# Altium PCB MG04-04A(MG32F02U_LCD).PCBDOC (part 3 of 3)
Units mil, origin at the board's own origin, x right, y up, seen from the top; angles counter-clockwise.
Board outline 5905.51 x 3543.31 mil, 2 copper layers (Top Layer, Bottom Layer); 293 components, 227 nets, 959 pads, 508 vias.
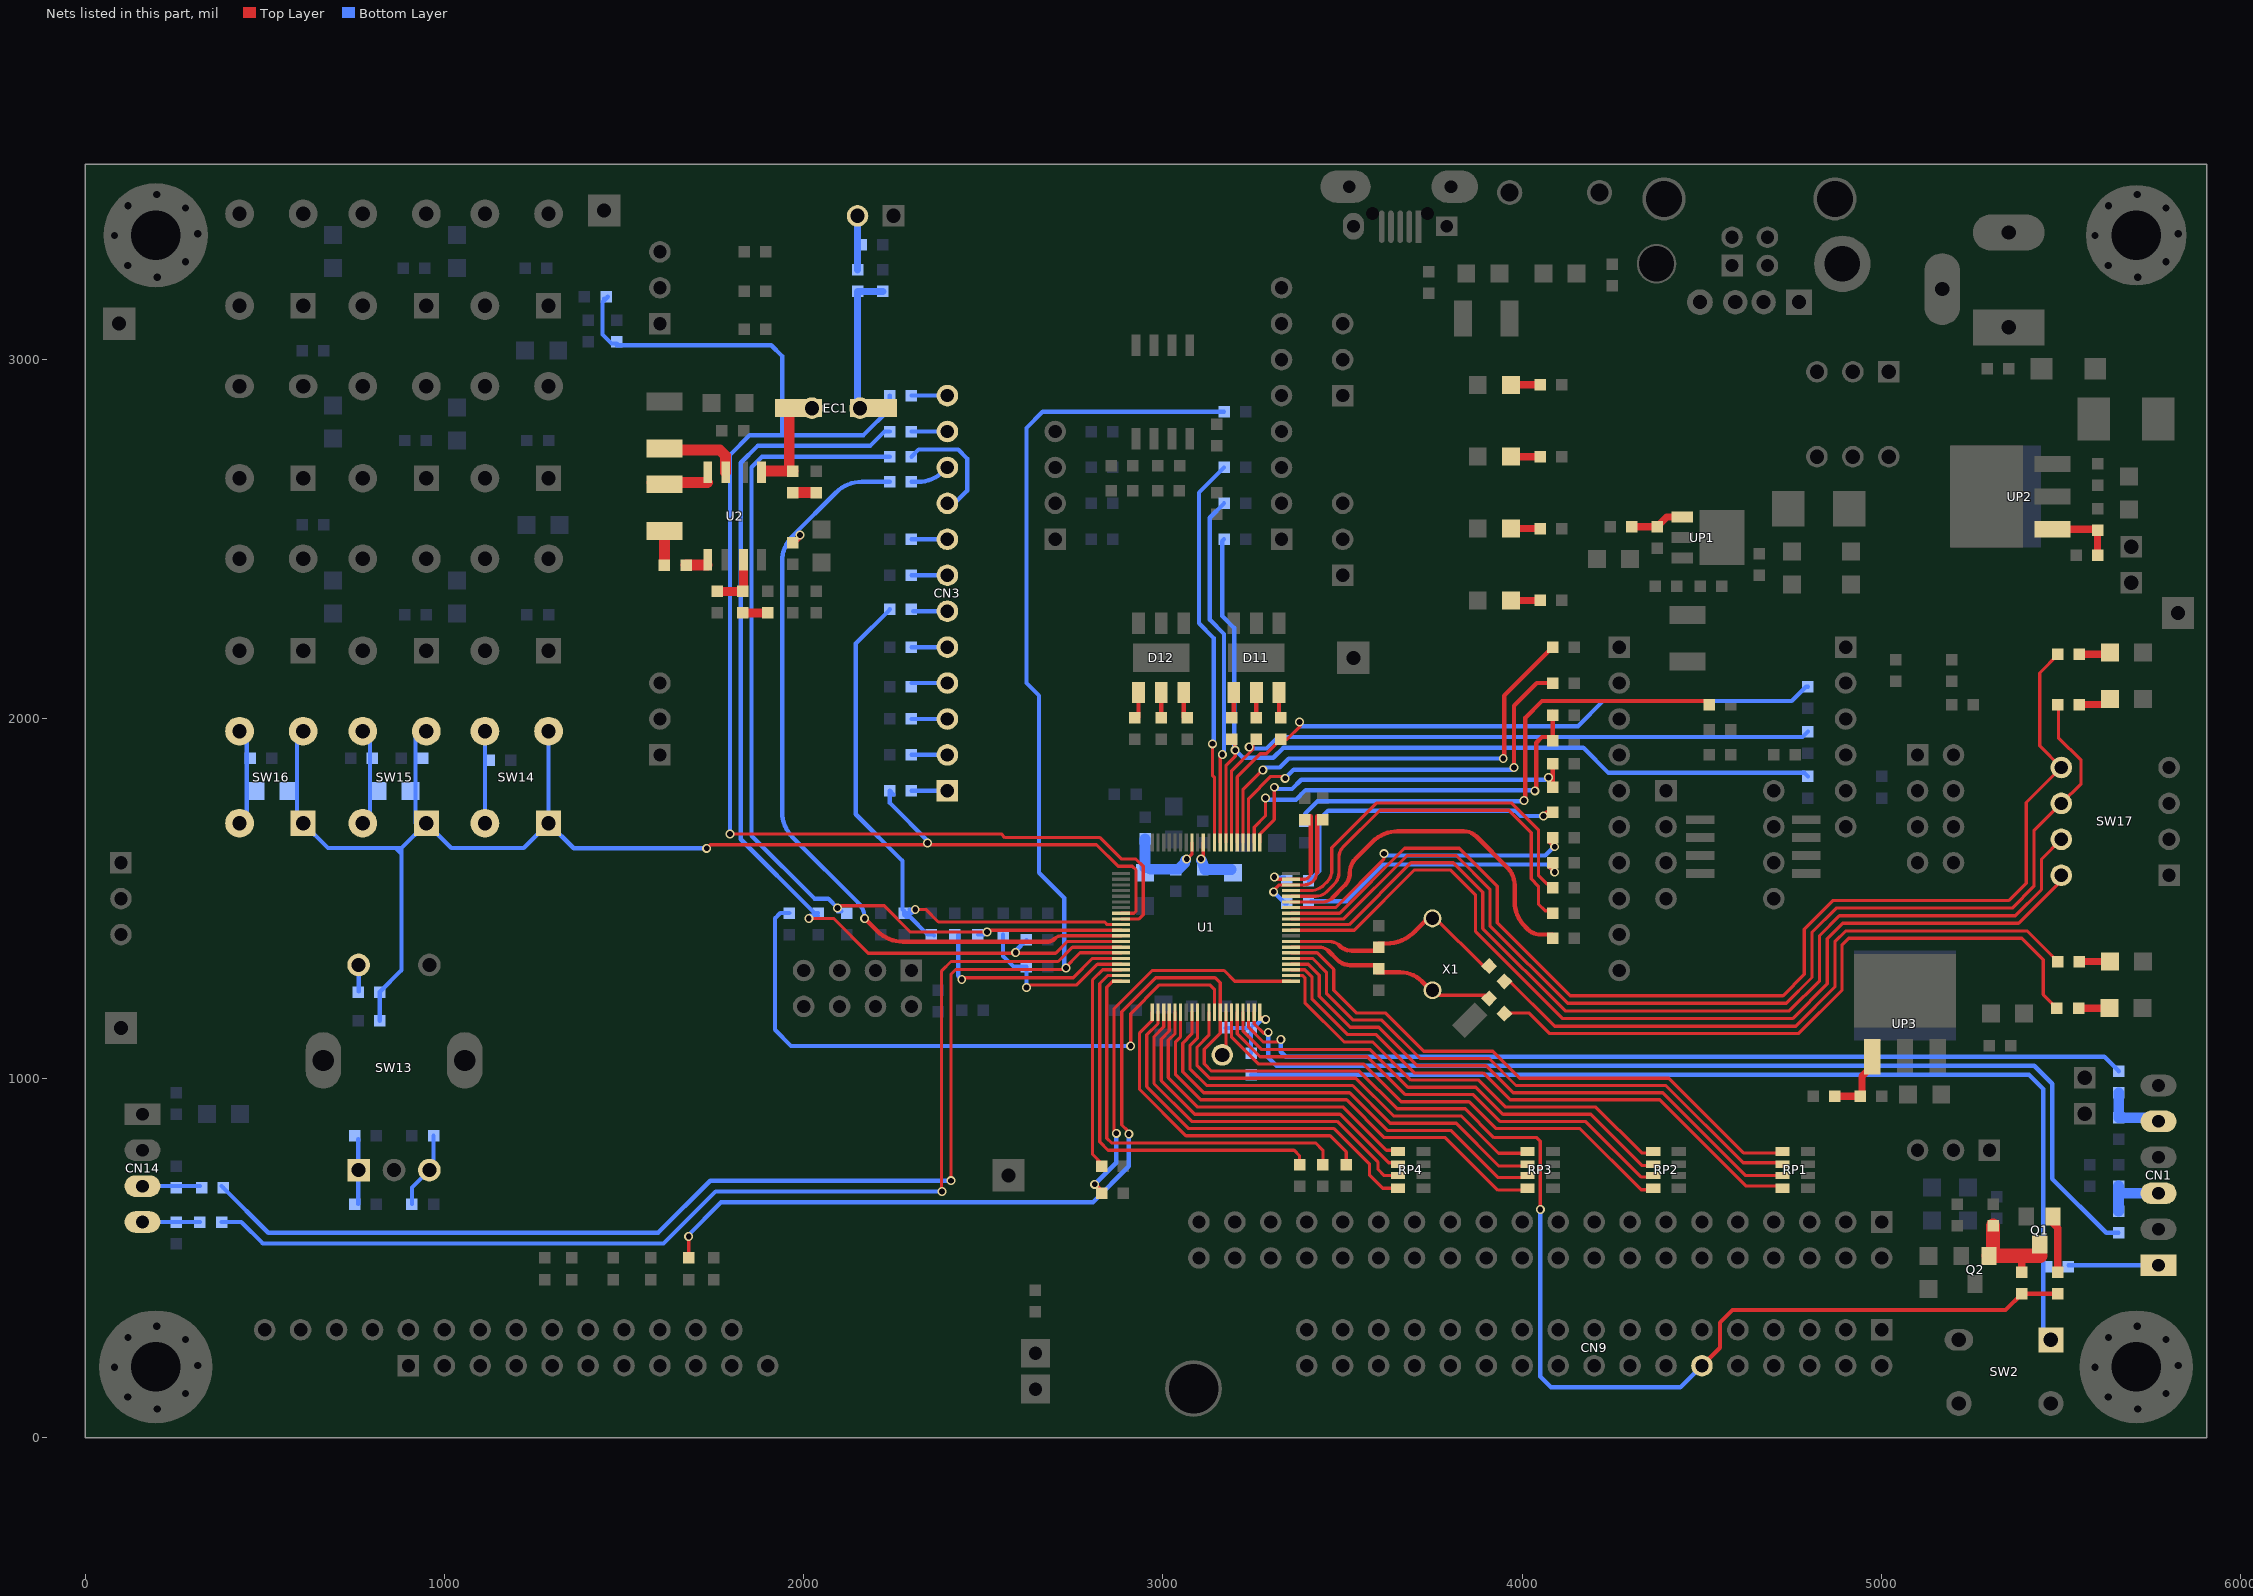
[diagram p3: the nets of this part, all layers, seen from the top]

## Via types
v1: diameter 25, hole 12, Top Layer to Bottom Layer, tented both sides, 253 vias
v2: diameter 25, hole 16, Top Layer to Bottom Layer, tented both sides, 83 vias
v3: diameter 20, hole 12, Top Layer to Bottom Layer, tented both sides, 77 vias
v4: diameter 35, hole 12, Top Layer to Bottom Layer, tented both sides, 64 vias
v5: diameter 40, hole 20, Top Layer to Bottom Layer, tented both sides, 16 vias
v6: diameter 30, hole 12, Top Layer to Bottom Layer, tented both sides, 13 vias
v7: diameter 28, hole 16, Top Layer to Bottom Layer, tented both sides, 2 vias

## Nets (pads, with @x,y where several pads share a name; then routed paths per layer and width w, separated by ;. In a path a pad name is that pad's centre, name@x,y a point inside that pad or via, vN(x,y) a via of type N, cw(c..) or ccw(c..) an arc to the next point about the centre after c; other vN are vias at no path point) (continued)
MG_PA14: C51.1 C52.1 C53.1 R37.2 R115.2 R123.2 SW14.1 SW14.3 SW15.1 SW15.3 SW16.1 SW16.3 U1.8 | length 4220.5
  Top Layer w9: v2(1730,1640) 1740,1650 2815,1650 2875,1590 2915,1590 2925,1580 2925,1465 2919.37,1459.37 U1.8@2883.78,1459.37
  Bottom Layer w12: SW16.1@590,1710 SW16.1@590,1727 ; SW16.3@590,1966 SW16.3@590,1949 ; SW16.3@607,1966 SW16.3@590,1949 ; R115.2@820,1160 R123.2@820,1240 881,1301 881,1625 ; SW15.1@920,1710 SW15.1@920,1716 ; SW15.3@920,1960 SW15.1@920,1716 ; SW15.1@930,1706 SW15.1@920,1716 ; SW15.1@930,1710 SW15.1@930,1720 ; SW14.3@1290,1966 SW14.1@1290,1710 ; v2(1730,1640) 1360,1640 SW14.1@1290,1710 ; R37.2@2250,1790 R37.2@2240,1800 2240,1766 v2@2350.5,1655.5 ; SW16.1@590,1727 SW16.1@607,1710 676,1641 865,1641 ; SW16.1@590,1727 SW16.3@590,1949 ; 865,1641 881,1641 ; 865,1641 881,1625 ; 881,1625 881,1641 ; 881,1641 SW15.1@950,1710 1019,1641 1221,1641 SW14.1@1290,1710
  other v2: 2345,1655
MG_PA15: C42.1 R46.2 R106.1 U1.9 | length 3836.7
  Top Layer w9: v2(1795,1680) 2550,1680 2560,1670 2825,1670 2885,1610 2925,1610 2945,1590 2945,1455 2933.62,1443.62 U1.9@2883.78,1443.62
  Bottom Layer w12: R106.1@1445,3170 1449,3170 R106.1@1449.5,3169.5 ; R106.1@1455,3175 R106.1@1449.5,3169.5 ; C42.1@1480,3040 1910,3040 1940,3010 1940,2790 ; C42.1@1480,3045 1465,3045 1440,3070 1440,3160 R106.1@1449.5,3169.5 ; v2(1795,1680) 1795,2735 1850,2790 1940,2790 ; R46.2@2240,2900 2240,2863.39 2166.61,2790 1940,2790
MG_PB0: R33.2 R47.2 R126.2 U1.10 | length 1701.7
  Top Layer w9: v2(2310.59,1470) 2340,1470 2375,1435 2837.87,1435 2845,1427.87 U1.10@2883.78,1427.87
  Bottom Layer w12: R33.2@2240,2305 2145,2210 2145,1735 2275,1605 2275,1470 2280,1465 R126.2@2280,1460 2280,1455 2285,1450 R126.2@2295,1450 ; R126.2@2295,1470 v2(2310.59,1470) 2300.59,1460 2285,1460 R126.2@2295,1450 ; R47.2@2362.5,1397.5 2360,1400 R47.2@2355,1400 2345,1400 R126.2@2295,1450
MG_PB1: R34.2 R48.2 R128.2 U1.11 | length 2639.8
  Top Layer w9: v2@2100.41,1480 2224.41,1480 2297.41,1407 v2(2510,1407) 2515.13,1412.13 2730,1412.13 ; 2690,1412.13 2730,1412.13 ; U1.11@2883.78,1412.13 2730,1412.13
  Bottom Layer w12: v2@2094.41,1465 R128.2@2105,1465 ; v2(2094.41,1474) 2068.41,1500 2030,1500 1855,1675 1855,2700.76 1884.24,2730 R34.2@2240,2730 ; R48.2@2485,1400 2503,1400 v2(2510,1407)
MG_PB2: R27.1 R35.2 U1.12 | length 2267.1
  Top Layer w9: 2699.18,1389.18 cw(c2716.56,1371.79) 2708.45,1395 ; 2710,1395 2708.45,1395 ; U1.12@2883.78,1396.38 2716.56,1396.38 ccw(c2716.56,1371.79) 2708.45,1395
  Top Layer w12: R27.1@1970,2484 v2@1995,2509 ; v2(2170,1445) 2205.73,1409.27 ccw(c2276.44,1479.98) 2276.44,1379.98 2676.98,1379.98 ccw(c2676.98,1411.37) 2699.15,1389.15
  Bottom Layer w12: v2(2170,1445) ccw(c2109.64,1445) 2152.32,1487.68 1969.29,1670.71 cw(c2040,1741.42) 1940,1741.42 1940,2438.58 cw(c2040,2438.58) 1969.29,2509.29 2090.9,2630.9 cw(c2161.61,2560.19) 2161.61,2660.19 R35.2@2240,2660.19
  other v2: 1990,2512
MG_PB3: R36.2 R129.2 R132.2 U1.13 | length 2792.1
  Top Layer w9: v2(2014.41,1445) 2083,1445 2180,1348 2701,1348 2733.63,1380.63 U1.13@2883.78,1380.63
  Bottom Layer w12: v2@2017,1452 R129.2@2039.59,1452 ; R129.2@2040,1460 2030,1460 1825,1665 1825,2713.19 1871.81,2760 2185,2760 2225,2800 R36.2@2240,2800 ; v2(2590,1350) 2590,1355 R132.2@2620,1385
MG_PB4: R59.1 U1.18 | length 621.3
  Top Layer w9: R59.1@2830,755 2830,762 2803.79,788.21 2803.79,1273.79 2831.89,1301.89 U1.18@2883.78,1301.89
MG_PB5: R63.1 U1.19 | length 1140.2
  Top Layer w9: U1.19@2883.78,1286.14 2846.14,1286.14 2823.79,1263.79 2823.79,823.21 2847,800 3080,800 ; 3046.72,800 3080,800 ; R63.1@3380,760 3380,785 3365,800 3080,800
MG_PB6: R62.1 U1.20 | length 1122.4
  Top Layer w9: U1.20@2883.78,1270.39 2860.39,1270.39 2843.79,1253.79 2843.79,833.21 2857,820 3425,820 3445,800 R62.1@3445,760
MG_PB7: R61.1 U1.21 | length 911.7
  Top Layer w9: U1.21@2970.39,1183.78 2970.39,1161.75 2935,1126.36 2935,968.73 3063.73,840 3465,840 3510,795 R61.1@3510,760
MG_PB8: RP4.4 U1.22 | length 1061.9
  Top Layer w9: U1.22@2986.14,1183.78 2986.14,1152.14 2955,1121 2955,977.01 3072.01,860 3476.27,860 3575,761.27 3575,730 3611.18,693.82 RP4.4@3649.57,693.82 ; RP4.4@3654.57,688.82 RP4.4@3649.57,693.82 ; RP4.4@3654.57,693.82 RP4.4@3649.57,693.82
MG_PB9: RP4.3 U1.23 | length 1014.8
  Top Layer w9: U1.23@3001.89,1183.78 3001.89,1143.1 2975,1116.21 2975,985.29 3080.29,880 3484.55,880 3598.77,765.78 3598.77,746.23 3615.75,729.25 RP4.3@3649.57,729.25 ; RP4.3@3648.82,730 RP4.3@3649.57,729.25 ; RP4.3@3654.57,724.25 RP4.3@3649.57,729.25 ; RP4.3@3654.57,729.25 RP4.3@3649.57,729.25
MG_PB10: RP4.2 U1.24 | length 957.7
  Top Layer w9: U1.24@3017.64,1183.78 3017.64,1131.64 2995,1109 2995,993.58 3088.58,900 3492.84,900 3627.84,765 3645.31,765 RP4.2@3654.57,755.75
MG_PB11: RP4.1 U1.25 | length 916.4
  Top Layer w9: U1.25@3033.39,1183.78 3033.39,1124.01 3015,1105.63 3015,1001.86 3096.86,920 3501.87,920 3621.87,800 3645.75,800 RP4.1@3654.57,791.18
MG_PB12: RP3.4 U1.26 | length 1292.2
  Top Layer w9: U1.26@3049.13,1183.78 3049.13,1116.13 3035,1102 3035,1010.15 3105.15,940 3511.12,940 3616.12,835 3786,835 3932.18,688.82 RP3.4@4014.57,688.82
MG_PB13: RP3.3 U1.28 | length 1257.4
  Top Layer w9: U1.28@3080.63,1183.78 3080.63,1123.63 3055,1098 3055,1018.43 3113.43,960 3519.41,960 3624.41,855 3801,855 3931.75,724.25 RP3.3@4014.57,724.25
MG_PB14: RP3.2 U1.29 | length 1217.7
  Top Layer w9: U1.29@3096.38,1183.78 3096.38,1112.38 3075,1091 3075,1026.72 3121.72,980 3527.69,980 3632.69,875 3816,875 3935.25,755.75 RP3.2@4014.57,755.75
MG_PB15: RP3.1 U1.31 | length 1183
  Top Layer w9: U1.31@3127.87,1183.78 3127.87,1119.87 3095,1087 3095,1035 3130,1000 3536.72,1000 3641.72,895 3830,895 3933.82,791.18 RP3.1@4014.57,791.18
MG_PC0: _ICKO1.1 U1.34 | length 128.7
  Top Layer w9: _ICKO1.1@3175,1054 _ICKO1.1@3175,1068.88 ; _ICKO1.1@3175.12,1070 U1.34@3175.12,1183.78
MG_PC1: RP2.4 U1.35 | length 1424.5
  Top Layer w9: U1.35@3190.87,1183.78 3190.87,1114.13 3265,1040 3557.72,1040 3662.72,935 3852,935 3927,860 4160.61,860 4330.61,690 RP2.4@4370,690
MG_PC2: RP2.3 U1.36 | length 1388.6
  Top Layer w9: U1.36@3206.61,1183.78 3206.61,1123.39 3270,1060 3568.43,1060 3673.43,955 3862.71,955 3937.71,880 4175.61,880 4330.18,725.43 RP2.3@4370,725.43
MG_PC3: RP2.2 U1.37 | length 1354.4
  Top Layer w9: U1.37@3222.36,1183.78 3222.36,1132.64 3275,1080 3576.72,1080 3681.72,975 3870.99,975 3945.99,900 4190.61,900 4333.69,756.93 RP2.2@4370,756.93
MG_PC4: R20.1 U1.38 | length 2537.1
  Top Layer w9: U1.38@3238.11,1183.78 3238.11,1141.89 3279,1101 v2@3328,1101
  Bottom Layer w12: v2(3328,1108) 3328,1074 3342,1060 5620,1060 R20.1@5660,1020
MG_PC5: R21.1 U1.39 | length 2876.3
  Top Layer w9: U1.39@3253.86,1183.78 3253.86,1151.14 3280,1125 v2@3293,1125
  Bottom Layer w12: v2(3293,1128) 3293,1058 3316,1035 5425,1035 5475,985 5475,720 5625,570 R21.1@5659.37,570
MG_PC6: C22.1 R15.1 R16.1 U1.40 | length 208.1
  Top Layer w9: U1.40@3271,1164 v2(3286,1164) ; U1.40@3274,1169 v2@3280,1169
  Bottom Layer w12: R15.1@3175.12,1140 C22.1@3245,1140 R16.1@3245,1070 ; C22.1@3251,1149 3260,1149 3275,1164 v2(3286,1164) v2@3292,1164
MG_PC7: R60.1 U1.41 | length 1095.5
  Top Layer w9: R60.1@2835,670 R60.1@2835,680 ; v2(2870,847) 2865,847 2863.79,848.21 2863.79,1193.79 2970,1300 3170,1300 3199.61,1270.39 U1.41@3356.22,1270.39
  Top Layer w12: v2(2810,705) R60.1@2822.5,692.5
  Bottom Layer w12: v2(2810,705) 2870,765 v2(2870,847)
MG_PC8: RP2.1 U1.42 | length 1259.3
  Top Layer w9: U1.42@3356.22,1286.14 3388.86,1286.14 3395,1280 3395,1210 3504,1101 3584,1101 3690,995 3879.28,995 3954.28,920 4204.61,920 4332.25,792.36 RP2.1@4370,792.36
MG_PC9: RP1.4 U1.43 | length 1658.9
  Top Layer w9: U1.43@3356.22,1301.89 3394.37,1301.89 3415,1281.26 3415,1220.15 3513.15,1122 3592.03,1122 3699.03,1015 3891,1015 3966,940 4383,940 4623,700 RP1.4@4730,700
MG_PC10: RP1.3 U1.44 | length 1646.4
  Top Layer w9: U1.44@3356.22,1317.64 3404.36,1317.64 3435,1287 3435,1228.43 3521.43,1142 3600.32,1142 3707.32,1035 3899.28,1035 3974.28,960 4391.28,960 4622.03,729.25 RP1.3@4724.57,729.25
MG_PC11: RP1.2 U1.45 | length 1637.9
  Top Layer w9: U1.45@3356.22,1333.39 3416.61,1333.39 3455,1295 3455,1236.72 3529.72,1162 3608.6,1162 3715.6,1055 3907.57,1055 3982.57,980 4399.57,980 4614.57,765 RP1.2@4724.57,765
MG_PC12: RP1.1 U1.46 | length 1632.9
  Top Layer w9: U1.46@3356.22,1349.13 3428.87,1349.13 3475,1303 3475,1245 3538,1182 3618.6,1182 3725.6,1075 3917.57,1075 3992.57,1000 4407.85,1000 4615.49,792.36 RP1.1@4724.57,792.36
MG_PC13: R74.2 R125.2 | length 1882.5
  Top Layer w9: R125.2@3950.11,1182 4018,1182 4075,1125 4769.25,1125 4890,1245.75 4890,1371.51 4908.49,1390 5390,1390 5450,1330 5450,1233 R74.2@5488,1195
MG_PC14: R76.2 R124.2 | length 1803.2
  Top Layer w9: R124.2@3963,1272 4090,1145 4760.97,1145 4870,1254.03 4870,1379.79 4900.21,1410 5405,1410 R76.2@5490,1325 ; R76.2@5492,1320 R76.2@5492,1325
MG_PD0: R83.1 U1.54 | length 836.6
  Top Layer w9: U1.54@3356.22,1475.12 3480.12,1475.12 ; 3480,1475 3480.12,1475.12 ; v2(3615,1625) 3615,1610 3480.12,1475.12
  Top Layer w12: R83.1@4074.71,1659.71 v2(4090,1644.41)
  Bottom Layer w12: v2@3615,1620 4064,1620 4088.41,1644.41 v2(4090,1644.41)
MG_PD1: R94.1 U1.55 | length 1001.8
  Top Layer w9: U1.55@3356.22,1490.87 3445,1490.87 ccw(c3445,1526.48) 3470.18,1501.3
  Top Layer w12: 3470.18,1501.3 3505.44,1536.55 ccw(c3469.8,1572.2) 3520.2,1572.2 cw(c3575.74,1572.2) 3536.47,1611.47 3583.26,1658.26 cw(c3653.97,1587.55) 3653.97,1687.55 ; 3651.59,1687.55 3653.97,1687.55 ; 3978.73,1536.54 3978.73,1492.69 ccw(c4078.73,1492.69) 4008.02,1421.98 4015.01,1414.99 ccw(c4051.21,1451.21) 4051.21,1400 R94.1@4085,1400 ; 3978.73,1537.54 ccw(c3906.31,1536.54) 3961.13,1583.87 3871.59,1673.41 ccw(c3837.45,1639.27) 3837.45,1687.55 3653.97,1687.55
MG_PD2: R91.1 U1.56 | length 1124.3
  Top Layer w9: U1.56@3356.22,1506.61 3425,1506.61 ; 3500.48,1642.48 ccw(c3525.82,1617.16) 3490,1617.16 3490,1573.46 cw(c3441.54,1573.46) 3475.81,1539.19 3456.12,1519.5 ; 3500.65,1642.65 3604,1746 3962.53,1746 4025,1683.53 4025,1555 4045,1535 4045,1485 4064,1466 R91.1@4086,1466 ; 3425,1506.61 ccw(c3425,1550.62) 3456.12,1519.5 ; 3425,1506.61 ccw(c3425,1550.62) 3456.12,1519.5
MG_PD3: R90.1 U1.57 | length 1122.1
  Top Layer w9: U1.57@3356.22,1522.36 3410,1522.36 ; R90.1@4085,1530 4075,1540 4070,1540 4045,1565 4045,1691.81 3970.81,1766 3594,1766 3470,1642 3470,1578 ; 3410,1522.36 ccw(c3410,1576.35) 3448.17,1538.17 ; 3410,1522.36 ccw(c3410,1576.35) 3448.17,1538.17 ; 3448.17,1538.17 3457.27,1547.27 ; 3457.27,1547.27 ccw(c3426.54,1578) 3470,1578 ; 3457.27,1547.27 ccw(c3426.54,1578) 3470,1578
MG_PD4: R19.2 R89.1 | length 750.4
  Top Layer w12: R89.1@4074.71,1589.71 v2(4090,1574.41)
  Bottom Layer w12: R19.2@3412,1493 3510,1493 3612,1595 4069.41,1595 v2(4090,1574.41)
MG_PD4X: R13.1 R19.1 U1.58 | length 355.9
  Top Layer w9: v2(3308,1519) 3308,1523 3323.11,1538.11 U1.58@3356.22,1538.11 3391.86,1538.11 ccw(c3391.86,1574.93) 3417.89,1548.89 ccw(c3393.84,1572.95) 3427.86,1572.95
  Top Layer w12: 3429,1572.95 R13.1@3429,1729
  Bottom Layer w12: v2(3308,1519) 3339.64,1487.36 R19.1@3345,1487.36
MG_PD5: R18.2 R87.1 | length 840.8
  Top Layer w12: v2@4065,1736 R87.1@4077,1748
  Bottom Layer w12: R18.2@3406.5,1548.5 3435,1577 3435,1720 3460,1745 3980,1745 3995,1730 v2(4059,1730)
MG_PD5X: R12.1 R18.1 U1.59 | length 302.7
  Top Layer w9: v2(3310,1560) 3316.14,1553.86 U1.59@3356.22,1553.86 3392.79,1553.86 ccw(c3392.79,1570.93) 3404.86,1558.86 ccw(c3387.96,1575.76) 3411.86,1575.76 ; v2@3310,1565 v2@3312.5,1562.5
  Top Layer w12: 3411,1572.31 3411,1729
  Bottom Layer w12: v2@3313,1558 R18.1@3338,1558
MG_PD6: R17.2 R85.1 | length 1426.1
  Top Layer w12: v2@4008,1768 4008,2003 4055,2050 4520,2050 R85.1@4530,2040
  Bottom Layer w12: R17.2@3395,1715 3395,1736 3430,1771 v2@4005,1771
  other v2: 4005,1773
MG_PD7: R82.1 R86.1 U1.61 | length 1010.8
  Top Layer w9: U1.61@3269.61,1656.22 3269.61,1679.61 3310,1720 v2(3310,1810)
  Top Layer w12: R86.1@4083,1808 R86.1@4085,1810 R82.1@4085,1875 R82.1@4085,1880
  Bottom Layer w12: v2@3310,1807 3312,1805 3359,1805 3385,1831 4063,1831 v2@4065,1833
  other v2: 4073,1837
MG_PD8: R81.1 R88.1 U1.62 | length 1156.1
  Top Layer w9: U1.62@3253.86,1656.22 3253.86,1698.86 3285,1730 v2(3285,1780)
  Top Layer w12: v2(4035,1800) 4039,1804 4039,1934 4055,1950 4085,1950 R81.1@4085,2010 R81.1@4085,2020
  Bottom Layer w12: v2@3285,1775 3370,1775 3397,1802 v2@4035,1802
MG_PD9: R80.1 U1.63 | length 1218.5
  Top Layer w9: U1.63@3238.11,1656.22 3238.11,1778.11 3300,1840 v2@3340,1840
  Top Layer w12: v2(3977,1865) 3977,2037 4040,2100 4065,2100 ; 4049,2100 4065,2100 ; R80.1@4085,2100 4065,2100
  Bottom Layer w12: v2(3340,1835) 3364,1859 v2@3977,1859
MG_PD10: R78.1 U1.64 | length 1268
  Top Layer w9: U1.64@3222.36,1656.22 3222.36,1803.36 v2@3274.5,1855.5
  Top Layer w12: v2@3950,1891 3950,2065 R78.1@4085,2200
  Bottom Layer w12: v2(3278,1858) 3285,1865 3325,1865 3350,1890 v2(3947,1890)
MG_PD11: R92.2 R96.1 U1.65 | length 1922.4
  Top Layer w9: U1.65@3206.61,1656.22 3206.61,1838.61 3271,1903 3287.46,1903 R92.2@3328,1943.54 3345.19,1943.54 3381.81,1980.17 v2@3381.81,1990
  Bottom Layer w12: v2@3382.5,1994.31 3382.67,1992.01 3383.59,1980 4155,1980 4225,2050 4690,2050 ; 4715,2050 4690,2050 ; R96.1@4795,2090 4790,2090 4750,2050 4690,2050
  other v2: 3380,1991.81
MG_PD12: R93.2 R97.1 U1.66 | length 1912.3
  Top Layer w9: U1.66@3190.87,1656.22 3190.87,1855.87 3250,1915 3250,1933.54 R93.2@3260,1943.54
  Bottom Layer w12: v2@3240,1917.54 3242.46,1920 3244.46,1918 3288,1918 3320,1950 4710,1950 ; 4730,1950 4710,1950 ; R97.1@4795,1965 4780,1950 4710,1950
  other v2: 3240,1922
MG_PD13: R52.2 R95.2 R98.1 U1.67 | length 2671.6
  Top Layer w9: U1.67@3175.12,1656.22 3175.12,1870.12 3201,1896 v2(3201,1913) ; R95.2@3190,1943.54 R95.2@3190,1945 ; v2@3200,1913 R95.2@3200,1943.54
  Bottom Layer w12: R52.2@3170,2500 3165,2495 3165,2286.46 3198,2253.46 v2@3198,1913 ; v2@3203.5,1911.5 3223,1892 3307,1892 3335,1920 4170,1920 4240,1850 4575,1850 ; 4700,1850 4575,1850 ; R98.1@4795,1840 4785,1850 4575,1850
MG_PD14: R53.2 U1.68 | length 989
  Top Layer w9: U1.68@3159.37,1656.22 3159.37,1895.37 v2(3165,1901)
  Bottom Layer w12: v2@3161,1895 3170,1904 3170,2236.46 3130,2276.46 3130,2560 R53.2@3170,2600
MG_PD15: R54.2 U1.69 | length 1091.1
  Top Layer w9: v2@3138,1928.81 3138,1842 3143.62,1836.38 U1.69@3143.62,1656.22
  Bottom Layer w12: v2(3138,1931) 3141,1934 3141,2225.46 3100,2266.46 3100,2630 R54.2@3170,2700
MG_PE0: R104.2 U1.14 | length 3231.1
  Top Layer w9: v2@2383.79,685 2383.79,1298.79 2410,1325 2708,1325 2747.88,1364.88 U1.14@2883.78,1364.88
  Bottom Layer w12: R104.2@380,600 435,600 495,540 1610,540 1755,685 v2(2385,685)
MG_PE1: R51.2 R103.2 U1.15 | length 5336.3
  Top Layer w9: v2(2410,715) 2410,1290 2422.5,1302.5 v2@2725,1302.5 ; v2@2725,1305 2769.13,1349.13 U1.15@2883.78,1349.13
  Bottom Layer w12: R103.2@380,700 R103.2@385,695 510,570 1595,570 1740,715 v2(2410,715) ; v2@2730,1304 2725,1309 2725,1501.81 2655,1571.81 2655,2065 2620,2100 2620,2810 2665,2855 R51.2@3170,2855
  other v2: 2730,1307
MG_PE2: R49.2 U1.16 | length 593
  Top Layer w9: v2@2440,1280 2750,1280 2803.39,1333.39 U1.16@2883.78,1333.39
  Bottom Layer w12: R49.2@2430,1400 2430,1285 2435,1280 v2@2435,1275
  other v2: 2440,1275
MG_PE3: R50.2 R133.2 U1.17 | length 495.1
  Top Layer w9: v2@2620,1250 v2@2625,1255 ; v2(2620,1253) 2627,1260 2760,1260 2817.64,1317.64 U1.17@2883.78,1317.64
  Bottom Layer w12: R50.2@2555,1400 2555,1340 2585,1310 R133.2@2620,1310 v2(2620,1253) v2@2620,1250
MG_PE8: R127.2 U1.32 | length 1789.9
  Top Layer w9: v2(2910,1090) 2910,1180 2990,1260 3130,1260 3143.62,1246.38 U1.32@3143.62,1183.78
  Bottom Layer w12: R127.2@1960,1460 1935,1460 1920,1445 1920,1135 1965,1090 v2(2910,1090)
MG_PE9: CN9.12 R66.1 R70.1 R73.1 U1.33 | length 5640.8
  Top Layer w9: R66.1@1680,500 v2(1680,560) ; v2@2900,855 2885,870 2885,1185 2980,1280 3145,1280 3159.37,1265.63 U1.33@3159.37,1183.78 3159.37,1125.37 3115,1081 3115,1040 3135,1020 3546.72,1020 3651.72,915 3841,915 3921,835 4040,835 4050,825 v2(4050,635)
  Top Layer w12: CN9.12@4500,200 4550,250 4550,320 4585,355 5345,355 R73.1@5390,400 R70.1@5490,400
  Bottom Layer w12: v2@1675,560 1770,655 2805,655 2905,755 v2(2905,845) ; v2(4050,635) 4050,170 4080,140 4440,140 CN9.12@4500,200
MG_PE12: SW17.8 U1.50 | length 2692
  Top Layer w9: U1.50@3356.22,1412.13 3532.13,1412.13 3700,1580 3800,1580 3870,1510 3870,1408.28 4112.09,1166.19 4752.19,1166.19 4848.81,1262.81 4848.81,1388.57 4891.43,1431.19 5381.19,1431.19 5500,1550 SW17.8@5500,1565
MG_PE13: SW17.7 U1.51 | length 2766.6
  Top Layer w9: U1.51@3356.22,1427.87 3517.87,1427.87 3690,1600 3808.28,1600 3890,1518.28 3890,1416.57 4119,1187.57 4743.33,1187.57 4827.43,1271.67 4827.43,1397.43 4882.57,1452.57 5372.33,1452.57 5445,1525.24 5445,1610 SW17.7@5500,1665
MG_PE14: R77.2 SW17.6 U1.52 | length 3160.3
  Top Layer w9: U1.52@3356.22,1443.62 3503.62,1443.62 3680,1620 3816.57,1620 3910,1526.57 3910,1424.85 4126.07,1208.79 4734.55,1208.79 4806.21,1280.45 4806.21,1406.21 4873.79,1473.79 5363.55,1473.79 5423.79,1534.03 5423.79,1688.79 SW17.6@5500,1765 5555,1820 5555,1885 5492,1948 R77.2@5492,2035
MG_PE15: R79.2 SW17.5 U1.53 | length 3277.8
  Top Layer w9: U1.53@3356.22,1459.37 3491.58,1459.37 3672.21,1640 3824.85,1640 3930,1534.85 3930,1433.14 4133.14,1230 4725.76,1230 4785,1289.24 4785,1415 4865,1495 5354.76,1495 5402.57,1542.81 5402.57,1767.57 SW17.5@5500,1865 5440,1925 5440,2128 R79.2@5492,2180
MG_VR0X: C19.1 C20.1 U1.71 | length 144.3
  Top Layer w9: v2(3106,1610) 3112.13,1616.13 U1.71@3112.13,1656.22
  Bottom Layer w30: v2@3107,1606 C20.1@3115,1586 ; C20.1@3116,1581 C19.1@3190,1581
MG_VREFX: C13.1 C14.1 R11.1 U1.73 | length 242.7
  Top Layer w9: v2@3066.84,1609.16 3080.63,1622.94 U1.73@3080.63,1656.22
  Bottom Layer w30: C13.1@2950,1586 R11.1@2950,1666 ; C13.1@2965,1582 3043.55,1582 3059.97,1598.41 v2@3063,1606
  other v2: 3066,1610
MX_G0: CN3.1 R37.1 | length 100
  Bottom Layer w12: R37.1@2300,1800 CN3.1@2400,1800
MX_G1: CN3.2 R38.1 | length 100
  Bottom Layer w12: R38.1@2300,1900 CN3.2@2400,1900
MX_G2: CN3.3 R39.1 | length 105
  Bottom Layer w12: R39.1@2300,2000 CN3.3@2400,2000 CN3.3@2400,1995
MX_G3: CN3.4 R40.1 | length 100
  Bottom Layer w12: R40.1@2300,2100 CN3.4@2400,2100
MX_G4: CN3.5 R41.1 | length 70
  Bottom Layer w12: R41.1@2300,2200 CN3.5@2370,2200
MX_G6: CN3.7 R42.1 | length 108.5
  Bottom Layer w12: R42.1@2300,2400 CN3.7@2400,2400 2405,2400 CN3.7@2402.5,2397.5
MX_G7: CN3.8 R43.1 | length 100
  Bottom Layer w12: R43.1@2300,2500 CN3.8@2400,2500
MX_G11: CN3.12 R46.1 | length 100
  Bottom Layer w12: R46.1@2300,2900 CN3.12@2400,2900
MX_MISO: CN3.9 R34.1 | length 327.3
  Bottom Layer w12: R34.1@2300,2730 2320,2750 2430,2750 2455,2725 2455,2635 CN3.9@2410,2590
MX_NSS: CN3.6 R33.1 | length 95
  Bottom Layer w12: R33.1@2305,2300 CN3.6@2400,2300
MX_RXD: CN3.11 R36.1 | length 100
  Bottom Layer w12: R36.1@2300,2800 CN3.11@2400,2800
MX_TXD: CN3.10 R35.1 | length 112.3
  Bottom Layer w12: R35.1@2300,2660 2318.58,2660 ccw(c2318.58,2760) 2389.29,2689.29 CN3.10@2400,2700
NetC28_1: C28.1 R25.1 | length 70
  Top Layer w25: R25.1@1830,2295 C28.1@1900,2295
NetC29_1: C29.1 EC1.1 U2.5 | length 262.1
  Top Layer w30: U2.5@1892.71,2690 C29.1@1970,2690 ; C29.1@1960,2695 1960,2855 1970,2865 EC1.1@1980.67,2865
NetC29_2: C29.2 R31.1 | length 65
  Top Layer w30: C29.2@1970,2630 R31.1@2035,2630
NetC30_1: C30.1 CN2.2 R26.2 | length 150
  Bottom Layer w20: R26.2@2150,3250 CN2.2@2150,3400
NetC52_2: C52.2 R121.2 SW15.2 SW15.4 | length 250
  Bottom Layer w12: SW15.2@793,1710 SW15.4@793,1960
NetC53_2: C53.2 R122.2 SW16.2 SW16.4 | length 272.6
  Bottom Layer w12: SW16.2@430,1710 450,1730 450,1946 SW16.4@430,1966
NetD1_1: D1.1 R1.2 | length 72
  Top Layer w20: D1.1@3980,2530 R1.2@4050,2530 ; R1.2@4050,2530 4051,2530.01 R1.2@4050,2530
NetD2_1: D2.1 R2.2 | length 77
  Top Layer w20: D2.1@3974,2730 R2.2@4050,2730 R2.2@4051,2730
NetD3_1: D3.1 R3.2 | length 77
  Top Layer w20: D3.1@3968,2330.01 R3.2@4045,2330.01
NetD4_1: D4.1 R4.2 | length 76
  Top Layer w20: D4.1@3974,2930 R4.2@4050,2930
NetD11_2: D11.2 R92.1 | length 70
  Top Layer w12: R92.1@3322.99,2003.54 D11.2@3322.99,2073.54
NetD11_4: D11.4 R93.1 | length 70
  Top Layer w12: R93.1@3260,2003.54 D11.4@3260,2073.54
NetD11_6: D11.6 R95.1 | length 70
  Top Layer w12: R95.1@3197.01,2003.54 D11.6@3197.01,2073.54
NetD12_2: D12.2 R100.1 | length 70
  Top Layer w12: R100.1@3057.99,2003.54 D12.2@3057.99,2073.54
NetD12_4: D12.4 R101.1 | length 70
  Top Layer w12: R101.1@2995,2003.54 D12.4@2995,2073.54
NetD12_6: D12.6 R102.1 | length 70
  Top Layer w12: R102.1@2932.01,2003.54 D12.6@2932.01,2073.54
NetEC1_2: EC1.2 R26.1 R32.1 | length 395
  Bottom Layer w20: EC1.2@2150,2865 R26.1@2150,3190 R32.1@2220,3190
NetQ1_1: Q1.1 R70.2 | length 141.2
  Top Layer w20: Q1.1@5477.4,596 5490,583.4 R70.2@5490,460
NetQ1_3: Q1.3 Q2.1 R67.1 R73.2 | length 253
  Top Layer w20: R73.2@5390,460 5390,506
  Top Layer w40: Q2.1@5297.4,506 Q2.1@5298.4,506 ; Q2.1@5310,510 R67.1@5310,590 ; Q2.1@5316,506 5390,506 5442,506
NetR5_2: R5.2 R7.1 UP2.1 | length 195.4
  Top Layer w20: UP2.1@5476,2528 5588,2528 R5.2@5601,2515 ; R7.1@5601,2460 R5.2@5601,2515 ; R5.2@5601,2525 R5.2@5601,2515
NetR6_2: R6.2 R8.1 UP1.1 | length 151.2
  Top Layer w20: R8.1@4305,2535 R6.2@4375,2535 4402,2562 UP1.1@4445,2562
NetR9_2: R9.2 R10.1 UP3.1 | length 160.4
  Top Layer w20: R10.1@4870,950 R9.2@4940,950 ; R9.2@4945,950 4945,1005 UP3.1@4970,1030
NetR24_1: R24.1 U2.1 | length 58.8
  Top Layer w30: R24.1@1672.71,2428.24 U2.1@1731.53,2428.24
NetR24_2: R24.2 TC4.1 | length 85
  Top Layer w30: R24.2@1612.71,2428.24 TC4.1@1612.71,2513.24
NetR25_2: R25.2 R29.1 U2.3 | length 158.8
  Top Layer w25: R29.1@1760,2355 R25.2@1830,2355 1832.71,2357.71 U2.3@1832.71,2442.65
NetR119_2: R119.2 SW14.2 SW14.4 | length 256
  Bottom Layer w12: SW14.2@1113,1710 SW14.4@1113,1966
NetTC4_2: TC4.2 U2.8 | length 155.7
  Top Layer w30: TC4.2@1577,2658.24 U2.8@1732.71,2658.24
NetTC5_1: TC5.1 U2.7 | length 192.2
  Top Layer w30: TC5.1@1642.71,2748.24 1766.76,2748.24 1782.71,2732.29 U2.7@1782.71,2686.65
RST_CHIP: R14.2 R16.2 SW2.1 | length 2898.6
  Bottom Layer w12: R16.2@3245,1010 5410,1010 5450,970 SW2.1@5450,293
SK_A: R116.1 R117.1 SW13.1 | length 180
  Bottom Layer w12: R117.1@760,650 R116.1@760,830
SK_B: R118.1 R120.1 SW13.3 | length 214.9
  Bottom Layer w12: R120.1@910,650 910,696.14 970,756.14 R118.1@970,840
SK_SW: R123.1 SW13.5 | length 73.9
  Bottom Layer w12: R123.1@761.58,1241.58 SW13.5@761.58,1315.43
SWCLK: CN1.5 R20.2 R23.1 | length 184.8
  Bottom Layer w30: R20.2@5660,960 R23.1@5660,890 5760.63,890 CN1.5@5770.63,880
SWDIO: CN1.3 R21.2 R22.1 | length 181.3
  Bottom Layer w30: R21.2@5659.37,630 5659.37,680 ; R22.1@5659.37,700 5659.37,680 ; CN1.3@5770.63,680 5659.37,680
SWSRST: CN1.1 R14.1 | length 250.6
  Bottom Layer w12: R14.1@5520,480 CN1.1@5770.63,480
TS_LED0: D7.2 R74.1 | length 86
  Top Layer w20: R74.1@5548,1195 D7.2@5634,1195
TS_LED1: D8.2 R76.1 | length 86
  Top Layer w20: R76.1@5550,1325 D8.2@5636,1325
TS_LED2: D9.2 R77.1 | length 86
  Top Layer w20: R77.1@5550,2040 D9.2@5634,2040 ; D9.2@5636,2050 D9.2@5638,2050
TS_LED3: D10.2 R79.1 | length 84
  Top Layer w20: R79.1@5550,2180 D10.2@5634,2180
U5V0_RXD: C41.1 CN14.3 R103.1 | length 160
  Bottom Layer w12: CN14.3@160,700 R103.1@320,700
U5V0_TXD: C40.1 CN14.4 R104.1 | length 160
  Bottom Layer w12: CN14.4@160,600 C40.1@254.49,600 R104.1@320,600
XIN: C17.1 R125.1 U1.47 X1.2 | length 573.3
  Top Layer w9: U1.47@3356.22,1364.88 3436.14,1364.88 cw(c3436.14,1331.14) 3460,1355 ; X1.2@3743.79,1231.21 R125.1@3898.79,1231.21
  Top Layer w12: 3460,1355 3485.88,1329.12 ccw(c3520,1363.28) 3520,1315 C17.1@3590,1315 ; C17.1@3595,1295 3660,1295 cw(c3660,1209.64) 3720.36,1270 X1.2@3745.36,1245
XOUT: C18.1 R124.1 U1.48 X1.1 | length 606.5
  Top Layer w9: U1.48@3356.22,1380.63 3464.34,1380.63 cw(c3464.34,1344.34) 3490,1370 ; X1.1@3759.71,1444.29 R124.1@3890.79,1313.21
  Top Layer w12: 3490,1370 ccw(c3526.21,1406.21) 3526.21,1355 C18.1@3600,1355 ; C18.1@3600,1375 3621,1375 ccw(c3621,1487) 3701.79,1409.44 X1.1@3743.68,1451.32
pads on no net: CJ2.2 CJ2.3 CJ2.8 CJ2.9 CN1.6 CN8.3 CN8.16 CN8.20 CN8.29 CN8.30 CN8.31 CN8.32 CN8.33 CN8.34 CN8.35 CN8.36 CN8.37 CN8.38 CN8.39 CN8.40 CN9.1 CN9.2 CN9.3 CN9.4 CN9.5 CN9.6 CN10.10 CN10.11 CN10.12 CN10.13 CN10.14 CN11.10 CN11.11 CN15.3 CN16.3 D11.0 D12.0 SW1.1 SW1.4 SW2.3 SW2.4 SW13.0

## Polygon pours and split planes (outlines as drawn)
GND on Top Layer "Top Layer-No Net" (hatched 90Degree grid 10 track 10, remove dead copper, pour order 1004): 25,25 5875,25 5875,3515 25,3515
+12V on Top Layer "Top Layer-No Net" (hatched 90Degree grid 10 track 10, remove dead copper, pour order 1002): 3735,2815 3755,2795 3800,2795 3845,2840 3800,2885 3770,2885 3735,2850
+12V on Top Layer "Top Layer-No Net" (hatched 90Degree grid 10 track 10, remove dead copper, pour order 1000): 3198.19,3370 3162.7,3334.51 3128.68,3334.51 3078.19,3385 3108.19,3415 3188.19,3415 3198.19,3405
+VDD on Top Layer "Top Layer-No Net" (hatched 90Degree grid 10 track 10, remove dead copper, pour order 1001): 3745,2425 3770,2450 3815,2450 3860,2405 3805,2350 3765,2350 3745,2370
+5V on Top Layer "Top Layer-No Net" (hatched 90Degree grid 10 track 10, remove dead copper, pour order 1000): 3750,2630 3775,2655 3820,2655 3865,2610 3810,2555 3770,2555 3750,2575
GND on Bottom Layer "Top Layer-No Net" (hatched 90Degree grid 10 track 10, remove dead copper, pour order 1004): 25,25 5875,25 5875,3515 25,3515
+12V on Bottom Layer "Top Layer-No Net" (hatched 90Degree grid 10 track 10, remove dead copper, pour order 1005): 3793.15,2800 3814.07,2820.93 3814.07,2865.93 3769.07,2910.93 3730,2871.85 3730,2815 3745,2800
+12V on Bottom Layer "Top Layer-No Net" (hatched 90Degree grid 10 track 10, remove dead copper, pour order 1003): 3107.7,3355.49 3128.19,3335 3168.19,3335 3238.19,3405 3218.19,3425 3133.19,3425 3107.7,3399.51
+VDD on Bottom Layer "Top Layer-No Net" (hatched 90Degree grid 10 track 10, remove dead copper, pour order 1004): 3821.81,2375 3796.81,2350 3751.81,2350 3706.81,2395 3761.81,2450 3801.81,2450 3821.81,2430
+5V on Bottom Layer "Top Layer-No Net" (hatched 90Degree grid 10 track 10, remove dead copper, pour order 1003): 3830,2630 3805,2655 3760,2655 3715,2610 3770,2555 3810,2555 3830,2575

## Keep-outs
Top Layer:
  lines w4: 1036.99,183 1062,183
Keep-Out Layer:
  circle w4: c526.22,145.63 r56.36
  circle w4: c2068.92,260.63 r56.36
  circle w4: c2258.69,160.63 r56.36

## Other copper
Top Layer:
  rectangle net GND: 3764,3344 3825,3398

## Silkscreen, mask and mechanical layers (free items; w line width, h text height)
Top Overlay:
  lines w6: 5201.81,710 5201.81,740 ; 5201.81,740 5191.81,730 5211.81,730 5201.81,740
  lines w10: 3430,3370 3430,2303.15 2600,2303.15 2600,3484.25 3430,3484.25 ; 2401.25,800.48 2401.25,935 2863,935 2863,800.48 2401.25,800.48 ; 2425,815 2425,920 2843,920 2843,815 2425,815
  lines w11.81: 1240,410 1240,1350 1615,1350 1615,410 1240,410 ; 1633.78,415 1800,415 1800,1355 1633.78,1355 1633.78,415
  lines w15: 334,1620 334,2082 1385,2082 1385,1620 335,1620 ; 1385,3525 335,3525 335,2109 1385,2109 1385,3526
  text "KEY0" at 1120,3460 h40
  text "KEY2" at 458.81,3455.18 h40
  text "KEY1" at 801.81,3455.18 h40
  text "USB Connector" at 3055,3395 h40
  text "GND" at 1401.81,3303 h40
  text "Extra DC" at 3945,3300 h50
  text "+12V MX" at 1708,3241.81 h40 r90
  text "+VDD_12C" at 3055,3225 h30
  text "Audio  Out" at 2070,3210 h40
  text "USB Connector" at 5030,3100 h40 r90
  text "DC 7-12V In" at 5110,3100 h40 r90
  text "WP" at 3211,3080 h30
  text "+5V" at 3570,3080 h40
  text "EEPROM" at 2680,3025 h40
  text "+5V_USB" at 3865,2995 h38
  text "GND" at 40,2990 h40
  text "SCL" at 3190,2980 h30
  text "+VDD_MX" at 3560,2980 h40
  text "KEY5" at 458.81,2975.18 h40
  text "KEY4" at 801.81,2975.18 h40
  text "KEY3" at 1141.81,2975.18 h40
  text "+12V/2A" at 5645,2955 h40
  text "+VDD MX" at 1710.81,2944 h40 r90
  text "GND" at 2260,2888.78 h30
  text "SDA" at 3190,2880 h30
  text "+VDD" at 3570,2880 h40
  text "+5V_LDO" at 5145,2795 h40
  text "+12V" at 3865,2790 h40
  text "RXD" at 2255,2788.78 h30
  text "X3" at 2771,2780 h30
  text "GND" at 3190,2780 h30
  text "TXD" at 2255,2683.78 h30
  text "X2" at 2771,2680 h30
  text "A2" at 3211,2680 h30
  text "Chip IO Power (3.3V)" at 4170,2670 h40
  text "Hot Key" at 305,2585 h50 r90
  text "MISO" at 2240,2580 h30
  text "X1" at 2771,2580 h30
  text "A1" at 3211,2580 h30
  text "+5V" at 3565,2580 h40
  text "+5V" at 3865,2580 h40
  text "+VDD_EP" at 3011.81,2499 h30
  text "KEY8" at 458.81,2495.18 h40
  text "KEY7" at 801.81,2495.18 h40
  text "KEY6" at 1141.81,2495.18 h40
  text "+VDD_12C" at 3550,2490 h38
  text "X0" at 2771,2480 h30
  text "A0" at 3211,2480 h30
  text "G7" at 2275,2478.78 h30
  text "+VDD" at 3865,2385 h40
  text "G6" at 2275,2383.78 h30
  text "+VDD" at 3575,2375 h40
  text "5V_IN" at 5500,2345 h40
  text "I2C Module (IR TX/RX)" at 2730,2330 h40
  text "+VDD_LDO" at 4145,2285 h35
  text "NSS" at 2250,2283.78 h30
  text "GND" at 5660,2280 h40
  text "+5V" at 4550,2275 h40
  text "G4" at 2280,2173.78 h30
  text "GND" at 1550,2170 h40
  text "D5" at 4360,2170 h30 r90
  text "3" at 5790,2170 h50
  text "CEN2" at 4990,2158 h30 r90
  text "G3" at 2280,2083.78 h30
  text "D6" at 4360,2080 h30 r90
  text "VDD_FS" at 5105,2080 h30 r90
  text "VDD_BLE2" at 5270,2080 h30 r90
  text "FS" at 4992,2071 h30 r90
  text "GND" at 3486,2060 h40
  text "2" at 5790,2030 h50
  text "KEY12" at 443.81,2020.18 h40
  text "KEY11" at 786.81,2020.18 h40
  text "KEY10" at 1126.81,2020.18 h40
  text "G2" at 2280,1983.78 h30
  text "D7" at 4360,1970 h30 r90
  text "AUX" at 4991.81,1965 h30 r90
  text "G1" at 2280,1888.78 h30
  text "D4" at 4360,1880 h30 r90
  text "DQS" at 4990,1865 h30 r90
  text "G0" at 2280,1783.78 h30
  text "D1" at 4360,1780 h30 r90
  text "RGB LED Display" at 2890,1738 h40
  text "RSTN" at 4990,1735 h30 r90
  text "Main Key" at 305,1720 h50 r90
  text "ARGB" at 127,1670 h50 r90
  text "Multi-Function Connector" at 1669,1665 h40
  text "CEN" at 4360,1660 h30 r90
  text "Xtal" at 3705,1646.55 h40
  text "DP" at 3395,1630 h30 r90
  text "DM" at 3445,1630 h30 r90
  text "GND" at 4990,1630 h30 r90
  text "+VDD" at 165,1580 h40
  text "D2" at 4360,1580 h30 r90
  text "CFG Setting" at 5430,1580 h40 r90
  text "BLE Connector-2" at 5310,1510 h40 r90
  text "ARGB" at 170,1480 h40
  text "D3" at 4360,1470 h30 r90
  text "Shuttle Key" at 727,1441.81 h40
  text "BLE Connector-1" at 1896,1381 h40
  text "GND" at 165,1380 h40
  text "D0" at 4360,1380 h30 r90
  text "LCD Power (3.3V)" at 4920,1380 h40
  text "SPI Flash" at 4475.8,1375.8 h40
  text "1" at 5790,1300 h50
  text "SCK" at 4360,1250 h30 r90
  text "GND" at 50,1210 h40
  text "0" at 5790,1180 h50
  text "SPI Connector" at 4335,1155 h40
  text "Test Clock Output" at 3230,1000 h40
  text "MG32F02U_LCD" at 2884,889 h45
  text "PW" at 300,880 h40
  text "LCD Power" at 5055,861.81 h40
  text "LCD  IF" at 3931.81,850 h40
  text "MG04-04A" at 2450,847 h50
  text "CLK" at 5664.63,846.81 h30 r90
  text "2021.05" at 2885,822 h30
  text "LCD_LDO" at 4865,781.81 h30
  text "GND" at 300,780 h40
  text "+5V" at 5361.81,760 h30
  text "VDD" at 5663.63,736.81 h30 r90
  text "GND" at 2405,735 h40
  text "SWD" at 5615,710 h40 r90
  text "BL" at 3210,685 h30 r90
  text "5V" at 3297,685 h30 r90
  text "RSTN" at 3342,685 h30 r90
  text "CS" at 3609,685 h30 r90
  text "B0" at 3794,685 h30 r90
  text "B1" at 3835,685 h30 r90
  text "B2" at 3912,685 h30 r90
  text "B3" at 3973,685 h30 r90
  text "B4" at 4156,685 h30 r90
  text "B5" at 4211,685 h30 r90
  text "B6" at 4279,685 h30 r90
  text "B7" at 4325,685 h30 r90
  text "RD" at 4518,685 h30 r90
  text "WR" at 4615,685 h30 r90
  text "RS" at 4685,685 h30 r90
  text "VCC" at 4917,685 h30 r90
  text "GND" at 5006,685 h30 r90
  text "+LCD_VCC" at 5198,685 h30
  text "RXD" at 300,680 h40
  text "SPI LCD Backlight Control" at 1745,630 h40 r90
  text "DIO" at 5664.63,629 h30 r90
  text "SPI LCD Backlight IF" at 1565,620 h40 r90
  text "TXD" at 300,580 h40
  text "+LCD_BL" at 5135,555 h30 r90
  text "GND" at 5664.63,519 h30 r90
  text "UART Connector-0" at 20,430 h40
  text "B8" at 4280,407 h30
  text "B9" at 4374.99,407 h30
  text "B10" at 4465,407 h30
  text "B11" at 4575,407 h30
  text "B12" at 4670,407 h30
  text "B13" at 4765,407 h30
  text "B14" at 4865,407 h30
  text "B15" at 4975,407 h30
  text "8080 LCD Module-1" at 2751,391.81 h40
  text "SWSRST" at 5620,380 h30 r90
  text "SDO" at 1010,370 h30 r90
  text "RS" at 1370,370 h30
  text "RSTN" at 1450,370 h30
  text "CS2" at 1575,370 h30
  text "GND" at 1675,370 h30
  text "VCC" at 1780,370 h30
  text "RS" at 3373.48,365.47 h30
  text "RD" at 3473.48,365.47 h30
  text "B0" at 3573.48,365.47 h30
  text "B2" at 3670.56,365.47 h30
  text "B4" at 3763.48,365.47 h30
  text "B6" at 3878.48,365.47 h30
  text "B8" at 3975.11,365.47 h30
  text "B10" at 4063.48,365.47 h30
  text "B12" at 4163.48,365.47 h30
  text "B14" at 4263.48,365.47 h30
  text "GND" at 4358.48,365.47 h30
  text "BL" at 4478.48,365.47 h30
  text "GND" at 4558.48,365.47 h30
  text "5V" at 4678.48,365.47 h30
  text "CTL2" at 1110,363.69 h30 r90
  text "SCK" at 1210,363.69 h30 r90
  text "SDI" at 1250,363.69 h30
  text "SPI LCD Module-1" at 1891.81,345 h40
  text "LCD Backlight" at 5120,320 h40
  text "8080 LCD Module-2" at 2741.81,229 h40
  text "CS" at 3368.48,110.47 h30
  text "WR" at 3473.48,110.47 h30
  text "RSTN" at 3553.48,110.47 h30
  text "B1" at 3688.48,110.47 h30
  text "B3" at 3778.48,110.47 h30
  text "B5" at 3873.48,110.47 h30
  text "B7" at 3973.48,110.47 h30
  text "B9" at 4068.48,110.47 h30
  text "B11" at 4163.48,110.47 h30
  text "B13" at 4262.48,110.47 h30
  text "B15" at 4369.48,110.47 h30
  text "PE8" at 4469.48,110.47 h30
  text "BL" at 4583.48,110.47 h30
  text "GND" at 4667.29,110.47 h30
  text "RS" at 1410,80 h30 r90
  text "SDI" at 1210,70 h30 r90
  text "GND" at 910,50 h30 r90
  text "VCC" at 1010,50 h30 r90
  text "SCK" at 1110,50 h30 r90
  text "SDO" at 1610,50 h30 r90
  text "CS2" at 1720,50 h30 r90
  text "SPI LCD Module-2" at 1891.81,45 h40
  text "CTL2" at 1510,35 h30 r90
  text "RSTN" at 1310,30 h30 r90
  text "LCD Reset" at 2530,25 h40
  text "Chip Reset" at 5230,20 h40
Bottom Overlay:
  text "+VDD_MG1" at 2830,1790 h40
  text "+VDD_BLE" at 2595,1110 h40
  text "+VDD_MG2" at 2955,1110 h40
  text "+VDD" at 595,920 h30
  text "+LCD_5V" at 5300,320 h40 r270
Mechanical 1:
  circle w4: c526.22,145.63 r56.36
  circle w4: c2068.92,260.63 r56.36
  circle w4: c2258.69,160.63 r56.36
  lines w10: 0,0 0,3543.31 5905.51,3543.31 5905.51,0 0,0

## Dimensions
0,0 to 5905.51,0 on Top Overlay
0,0 to 0,3543.31 on Top Overlay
